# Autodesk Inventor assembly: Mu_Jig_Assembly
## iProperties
Shininess: 64.0
Length Units: 11272
Angle Units: 11279
Time Units: 11290
Mass Units: 11286
Length Display Precision: 3
Angle Display Precision: 2
Compacted: True
Part Number: Mu_Jig_Assembly
Document SubType Name: Assembly
Created: 2004-08
Designer: John Blackburn
Manufacturer: Standard
Standards Organization: Custom
Density: 0.0
Volumn: 0.0
Area: 0.0
PropertySet Name: Model Information
Control State: 0
Master: False
Checked Out: False
Author: John Blackburn
